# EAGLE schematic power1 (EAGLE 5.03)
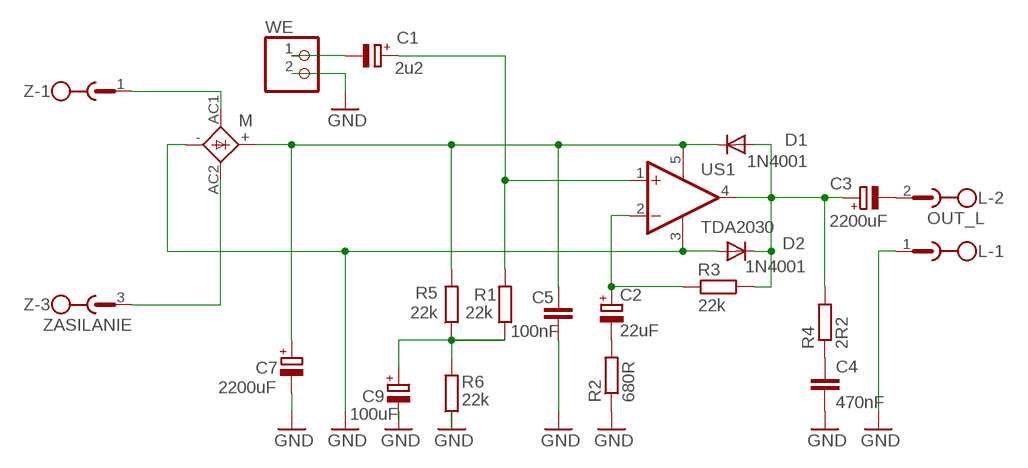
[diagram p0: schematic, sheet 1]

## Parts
C1  2u2  CPOL-EUE2.5-7  [E2,5-7]
C2  22uF  CPOL-EUE2.5-7  [E2,5-7]
C3  2200uF  CPOL-EUE7.5-16  [E7,5-16]
C4  470nF  C-EU050-030X075  [C050-030X075]
C5  100nF  C-EU050-030X075  [C050-030X075]
C7  2200uF  CPOL-EUE7.5-16  [E7,5-16]
C9  100uF  CPOL-EUE2.5-7  [E2,5-7]
D1  1N4001  1N4148DO35-10  [DO35-10]
D2  1N4001  1N4148DO35-10  [DO35-10]
L  OUT_L  MSTBV2  [MSTBV2]
M  KBU  [KBU]
R1  22k  R-EU_0207/15  [0207/15]
R2  680R  R-EU_0207/10  [0207/10]
R3  22k  R-EU_0207/10  [0207/10]
R4  2R2  R-EU_0207/10  [0207/10]
R5  22k  R-EU_0207/10  [0207/10]
R6  22k  R-EU_0207/10  [0207/10]
US1  TDA2030  TDA2030V  [CB360]
WE  PINHD-1X2  [1X02]
Z  ZASILANIE  MSTBV3  [MSTBV3]

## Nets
GND: C4.2 C5.2 C7.- C9.- D2.A L.1 M.- R2.1 R6.1 US1.3(GND) WE.2
N$1: C1.- WE.1
N$2: C1.+ R1.2 US1.1(+IN)
N$4: C3.- L.2
N$6: C9.+ R1.1 R5.1 R6.2
N$7: M.AC1 Z.1
N$8: C2.+ R3.2 US1.2(-IN)
N$10: C3.+ D1.A D2.C R3.1 R4.2 US1.4(OUT)
N$12: C4.1 R4.1
N$13: C2.- R2.2
N$14: M.AC2 Z.3
N$15: C5.1 C7.+ D1.C M.+ R5.2 US1.5(V+)
Unconnected: Z.2

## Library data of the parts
C1-C3 C7 C9 = rcl:CPOL-EU: POLARIZED CAPACITOR, European symbol
C4 C5 = rcl:C-EU: CAPACITOR, European symbol
D1 D2 = diode:1N4148: DIODE
L = con-phoenix-508:MSTBV2: PHOENIX
M = rectifier:KBU: DIOTEC RECTIFIER
R1-R6 = rcl:R-EU_: RESISTOR, European symbol
US1 = linear:TDA2030: Power OP AMP
WE = pinhead:PINHD-1X2: PIN HEADER
Z = con-phoenix-508:MSTBV3: PHOENIX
